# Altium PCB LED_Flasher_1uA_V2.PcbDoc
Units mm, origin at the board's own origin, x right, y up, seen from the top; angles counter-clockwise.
Board outline 16.51 x 17.78 mm, 2 copper layers (Top Layer, Bottom Layer); 21 components, 14 nets, 45 pads, 0 vias.
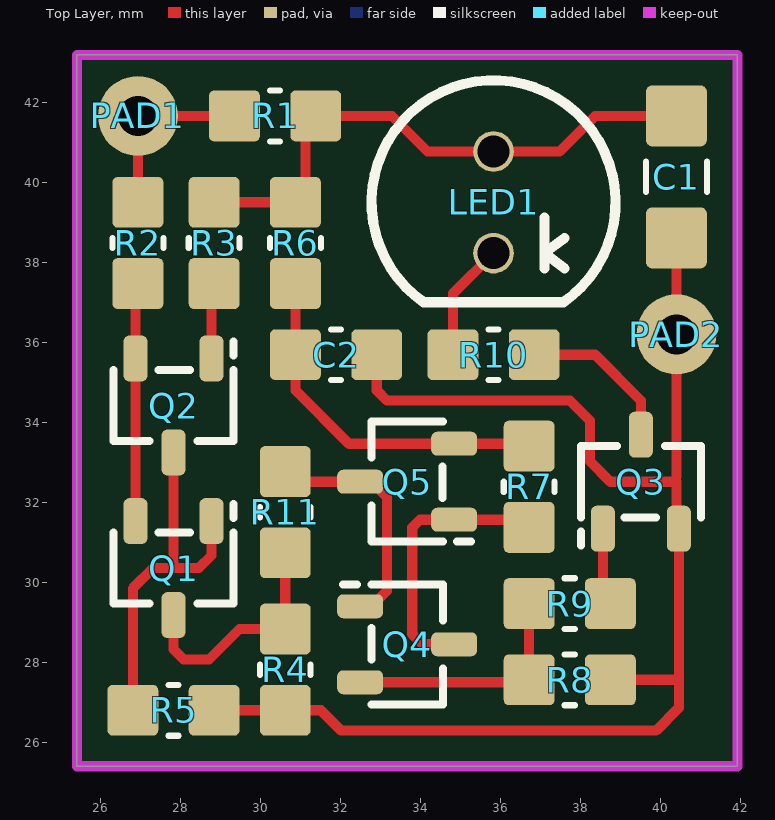
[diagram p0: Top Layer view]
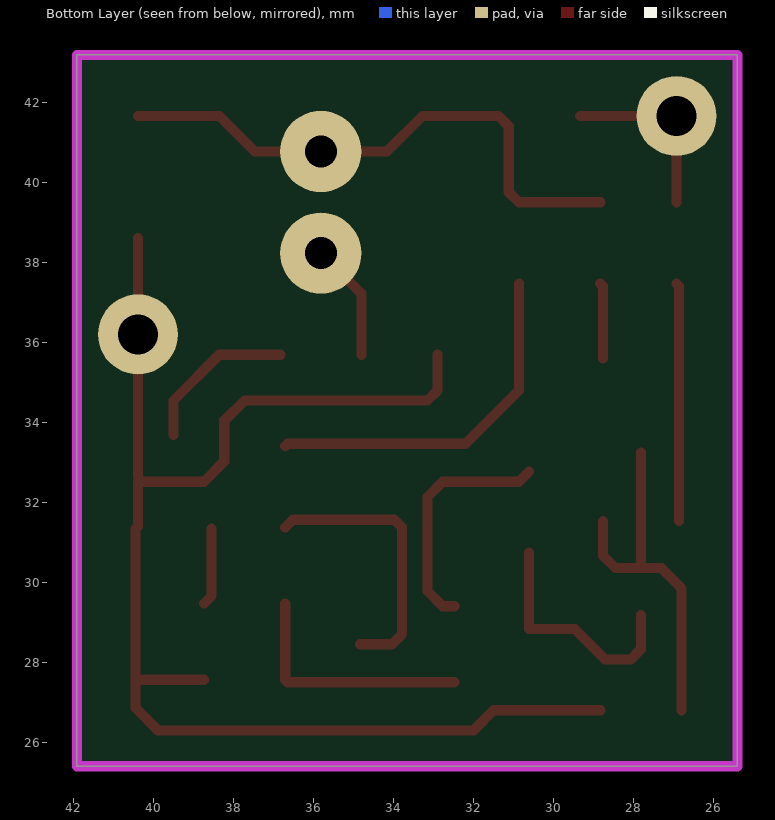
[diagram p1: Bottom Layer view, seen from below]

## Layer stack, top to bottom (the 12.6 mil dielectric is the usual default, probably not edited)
Top Layer: signal copper 0.0356
Dielectric: dielectric 0.32, FR-4, Dk 4.8
Bottom Layer: signal copper 0.0356

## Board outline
25.4,25.4 25.4,43.18 41.91,43.18 41.91,25.4

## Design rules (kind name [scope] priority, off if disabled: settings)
Clearance [All] p1: gap=0.254
PolygonConnect [All] p1: connectstyle=Relief reliefconductorwidth=0.254 reliefentries=4 polygonreliefangle="90 Angle"
RoutingVias [All] p1: holewidth=0.711 width=1.27 viastyle="Through Hole" minholewidth=0.711 minwidth=1.27 maxholewidth=0.711 maxwidth=1.27
SilkscreenOverComponentPads [All] p1: minsilkscreentomaskgap=0.025
SolderMaskExpansion [All] p1: expansion=0.102
Width [All] p1: maxlimit=0.254 minlimit=0.254 preferedwidth=0.254
27 further rules are at their usual default settings.

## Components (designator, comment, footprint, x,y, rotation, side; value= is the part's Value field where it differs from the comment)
C1 "1u" 1206 40.386,40.132 r90 top
C2 "100n" 0805 31.877,35.687 r0 top
LED1 "Red LED" LED5MM-REDUCEDPADS 35.814,39.497 r0 top
PAD1 "DNF" PAD2MM+1MMHOLE 26.924,41.656 r270 top
PAD2 "DNF" PAD2MM+1MMHOLE 40.386,36.195 r0 top
Q1 "BC856" SOT23-3 27.813,30.353 r90 top
Q2 "BC856" SOT23-3 27.813,34.417 r90 top
Q3 "BC846" SOT23-3 39.497,32.512 r270 top
Q4 "BC846" SOT23-3 33.655,28.448 r180 top
Q5 "BC856" SOT23-3 33.655,32.512 r0 top
R1 "2M2" 0805-RES 30.353,41.656 r180 top
R2 "220k" 0805-RES 26.924,38.481 r90 top
R3 "2M2" 0805-RES 28.829,38.481 r90 top
R4 "10M" 0805-RES 30.607,27.813 r90 top
R5 "10M" 0805-RES 27.813,26.797 r180 top
R6 "2M2" 0805-RES 30.861,38.481 r90 top
R7 "220k" 0805-RES 36.703,32.385 r270 top
R8 "100k" 0805-RES 37.719,27.559 r0 top
R9 "1k" 0805-RES 37.719,29.464 r0 top
R10 "100" 0805-RES 35.814,35.687 r180 top
R11 "2M2" 0805-RES 30.607,31.75 r90 top

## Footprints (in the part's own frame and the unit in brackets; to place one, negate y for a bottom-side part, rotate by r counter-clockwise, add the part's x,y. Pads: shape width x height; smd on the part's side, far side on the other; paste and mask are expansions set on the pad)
0805 [mil]
  rrect20% 50x50 smd: 1(-40,0) 2(40,0)
  silkscreen extent -5,-25 5,25, body extent -40,-25 40,25, height 49
0805-RES [mil]
  rrect20% 50x50 smd: 1(-40,0) 2(40,0)
  silkscreen extent -5,-25 5,25, body extent -40,-25 40,25, height 20
1206 [mil]
  rrect20% 60x60 smd: 1(-60,0) 2(60,0)
  silkscreen extent -15,-30 15,30, body extent -60,-30 60,30, height 59
LED5MM-REDUCEDPADS [mil] "LED 5mm with full-size pad on one side of the PCB only."
  round 40 / inner round 80 / far side round 80 hole 31.5: A(0,50) K(0,-50)
  silkscreen extent -120,-98 120,120, body extent -120,-99 121,120, height 256
PAD2MM+1MMHOLE [mm] "PAD"
  round 2 hole 1: 1(0,0)
  body extent -1,-1 0.99,1, height 0.01
SOT23-3 [mm]
  rrect50% 1.15x0.6 smd: 1(1.175,-0.95) 2(1.175,0.95) 3(-1.175,0)
  silkscreen extent -0.89,-1.5 1.6,1.5, body extent -1.39,-1.52 1.41,1.53, height 1.3

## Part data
C1: library part "CAP 1206", "CAP 1206"
C2: library part "CAP 0805", "CAP 0805"
LED1: library part LED
PAD1 PAD2: library part "Pad 2mm 1mm hole", "A single pad."
Q1 Q2 Q5: library part Transistor_BC856, "BC856 PNP transistor"
Q3 Q4: library part Transistor_BC846, "BC846 NPN transistor"
R1 R2 R3 R4 R5 R6 R7 R8 R9 R10 R11: library part "RES 0805", "Resistor 0805"

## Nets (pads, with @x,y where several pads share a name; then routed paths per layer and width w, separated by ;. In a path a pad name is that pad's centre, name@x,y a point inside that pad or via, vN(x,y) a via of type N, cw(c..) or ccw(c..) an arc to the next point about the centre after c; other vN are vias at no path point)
NetC1_1: C1.1 C2.2 PAD2.1 Q3.2 R4.1 R5.1 R8.2 | length 35.3
  Top Layer w0.254: R5.1 R4.1 31.496,26.797 32.004,26.289 39.878,26.289 40.447,26.858 40.447,27.559 ; C2.2 32.893,34.798 33.147,34.544 37.719,34.544 38.227,34.036 38.227,33.02 38.735,32.512 40.386,32.512 Q3.2@40.386,31.398 ; R8.2 40.447,27.559 ; 40.386,32.639 PAD2.1 C1.1 ; Q3.2 40.447,27.559
NetC1_2: C1.2 LED1.A R1.1 R3.2 R6.2 | length 14.2
  Top Layer w0.254: R3.2 R6.2 31.115,39.751 31.115,41.402 R1.1 33.274,41.656 34.163,40.767 LED1.A 37.465,40.767 38.354,41.656 C1.2
NetC2_1: C2.1 Q5.2 R6.1 R7.1 | length 9.1
  Top Layer w0.254: R6.1 C2.1 30.861,34.798 32.197,33.462 Q5.2 36.642,33.462 R7.1
NetLED1_K: LED1.K R10.2 | length 3
  Top Layer w0.254: R10.2 34.798,37.211 LED1.K
NetPAD1_1: PAD1.1 R1.2 R2.2 | length 4.6
  Top Layer w0.254: R2.2 PAD1.1 R1.2
NetQ1_1: Q1.1 Q2.3 R5.2 | length 9.1
  Top Layer w0.254: R5.2 26.797,29.845 27.305,30.353 27.813,30.353 ; Q2.3 27.813,30.353 ; Q1.1 28.763,30.668 28.448,30.353 27.813,30.353
NetQ1_2: Q1.2 Q2.2 R2.1 | length 6
  Top Layer w0.254: Q1.2 Q2.2 26.863,37.404 R2.1
NetQ1_3: Q1.3 R4.2 R11.1 | length 6
  Top Layer w0.254: Q1.3 27.813,28.321 28.067,28.067 28.702,28.067 29.464,28.829 R4.2 R11.1
NetQ2_1: Q2.1 R3.1 | length 1.9
  Top Layer w0.254: Q2.1 28.763,37.399 R3.1
NetQ3_1: Q3.1 R9.2 | length 2
  Top Layer w0.254: Q3.1 38.547,29.652 R9.2
NetQ3_3: Q3.3 R10.1 | length 4
  Top Layer w0.254: R10.1 38.354,35.687 39.497,34.544 Q3.3
NetQ4_1: Q4.1 Q5.3 R11.2 | length 6
  Top Layer w0.254: R11.2 30.861,32.512 Q5.3 32.766,32.512 33.147,32.131 33.147,29.779 32.766,29.398 Q4.1
NetQ4_2: Q4.2 R8.1 R9.1 | length 6.2
  Top Layer w0.254: Q4.2 36.642,27.498 R8.1 R9.1
NetQ4_3: Q4.3 Q5.1 R7.2 | length 6.9
  Top Layer w0.254: Q4.3 34.036,28.448 33.782,28.702 33.782,31.369 33.975,31.562 Q5.1 36.51,31.562 R7.2

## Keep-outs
Keep-Out Layer:
  the board outline again, w0.254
